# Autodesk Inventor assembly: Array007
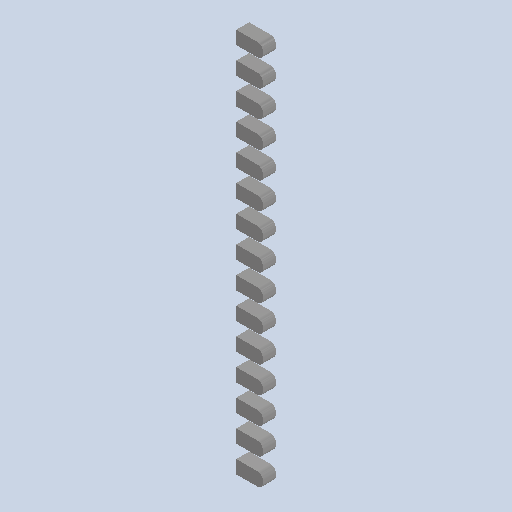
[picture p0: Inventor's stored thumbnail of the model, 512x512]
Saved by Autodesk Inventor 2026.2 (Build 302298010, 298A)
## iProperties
Created: 2026-10
Part Number: Array007
Document SubType Name: Assembly
Designer: mel
Author: mel
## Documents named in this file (16)
- D:\travail\année 2026-2027\1 sti2d IT\poubelle à verre\raspberry-pico-2-microcontroller-rp2350-1.snapshot.5\raspberry_pico_2\raspberry_pico_2\Array007.iam
- D:\travail\année 2026-2027\1 sti2d IT\poubelle à verre\raspberry-pico-2-microcontroller-rp2350-1.snapshot.5\raspberry_pico_2\raspberry_pico_2\Fillet045.ipt
- D:\travail\année 2026-2027\1 sti2d IT\poubelle à verre\raspberry-pico-2-microcontroller-rp2350-1.snapshot.5\raspberry_pico_2\raspberry_pico_2\Fillet046.ipt
- D:\travail\année 2026-2027\1 sti2d IT\poubelle à verre\raspberry-pico-2-microcontroller-rp2350-1.snapshot.5\raspberry_pico_2\raspberry_pico_2\Fillet047.ipt
- D:\travail\année 2026-2027\1 sti2d IT\poubelle à verre\raspberry-pico-2-microcontroller-rp2350-1.snapshot.5\raspberry_pico_2\raspberry_pico_2\Fillet048.ipt
- D:\travail\année 2026-2027\1 sti2d IT\poubelle à verre\raspberry-pico-2-microcontroller-rp2350-1.snapshot.5\raspberry_pico_2\raspberry_pico_2\Fillet049.ipt
- D:\travail\année 2026-2027\1 sti2d IT\poubelle à verre\raspberry-pico-2-microcontroller-rp2350-1.snapshot.5\raspberry_pico_2\raspberry_pico_2\Fillet050.ipt
- D:\travail\année 2026-2027\1 sti2d IT\poubelle à verre\raspberry-pico-2-microcontroller-rp2350-1.snapshot.5\raspberry_pico_2\raspberry_pico_2\Fillet051.ipt
- D:\travail\année 2026-2027\1 sti2d IT\poubelle à verre\raspberry-pico-2-microcontroller-rp2350-1.snapshot.5\raspberry_pico_2\raspberry_pico_2\Fillet052.ipt
- D:\travail\année 2026-2027\1 sti2d IT\poubelle à verre\raspberry-pico-2-microcontroller-rp2350-1.snapshot.5\raspberry_pico_2\raspberry_pico_2\Fillet053.ipt
- D:\travail\année 2026-2027\1 sti2d IT\poubelle à verre\raspberry-pico-2-microcontroller-rp2350-1.snapshot.5\raspberry_pico_2\raspberry_pico_2\Fillet054.ipt
- D:\travail\année 2026-2027\1 sti2d IT\poubelle à verre\raspberry-pico-2-microcontroller-rp2350-1.snapshot.5\raspberry_pico_2\raspberry_pico_2\Fillet055.ipt
- D:\travail\année 2026-2027\1 sti2d IT\poubelle à verre\raspberry-pico-2-microcontroller-rp2350-1.snapshot.5\raspberry_pico_2\raspberry_pico_2\Fillet056.ipt
- D:\travail\année 2026-2027\1 sti2d IT\poubelle à verre\raspberry-pico-2-microcontroller-rp2350-1.snapshot.5\raspberry_pico_2\raspberry_pico_2\Fillet057.ipt
- D:\travail\année 2026-2027\1 sti2d IT\poubelle à verre\raspberry-pico-2-microcontroller-rp2350-1.snapshot.5\raspberry_pico_2\raspberry_pico_2\Fillet058.ipt
- D:\travail\année 2026-2027\1 sti2d IT\poubelle à verre\raspberry-pico-2-microcontroller-rp2350-1.snapshot.5\raspberry_pico_2\raspberry_pico_2\Fillet059.ipt
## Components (15 placed, 15 different names)
1. 2738
2. 2739
3. 2740
4. 2741
5. 2742
6. 2743
7. 2744
8. 2745
9. 2746
10. 2747
11. 2748
12. 2749
13. 2750
14. 2751
15. 2752
